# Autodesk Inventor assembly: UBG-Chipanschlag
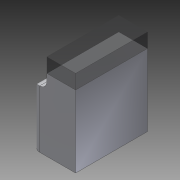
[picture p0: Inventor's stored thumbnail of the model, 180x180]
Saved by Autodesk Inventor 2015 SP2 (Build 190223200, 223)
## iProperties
Created: 2016-01
Part Number: UBG-Chipanschlag
Document SubType Name: Assembly
Designer: rYan
Author: rYan
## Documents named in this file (3)
- D:\TIGERs GIT\Hardware\mechanik\2016\Inventor\Kicker\UBG-Chipanschlag.iam
- D:\TIGERs GIT\Hardware\mechanik\2016\Inventor\Kaufteile\Gelpad 10x4.ipt
- D:\TIGERs GIT\Hardware\mechanik\2016\Inventor\Kicker\Chipanschlag.ipt
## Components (2 placed, 2 different names)
1. Chipanschlag:1 — Passend:1, Fluchtend:2, Fluchtend:3
2. Gelpad 10x4:1 — Passend:1, Fluchtend:2, Fluchtend:3
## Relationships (3: Flush 2, Mate 1)
- Passend:1 [Mate]: Chipanschlag:1 ↔ Gelpad 10x4:1
- Fluchtend:2 [Flush]: Chipanschlag:1 ↔ Gelpad 10x4:1
- Fluchtend:3 [Flush]: Chipanschlag:1 ↔ Gelpad 10x4:1
